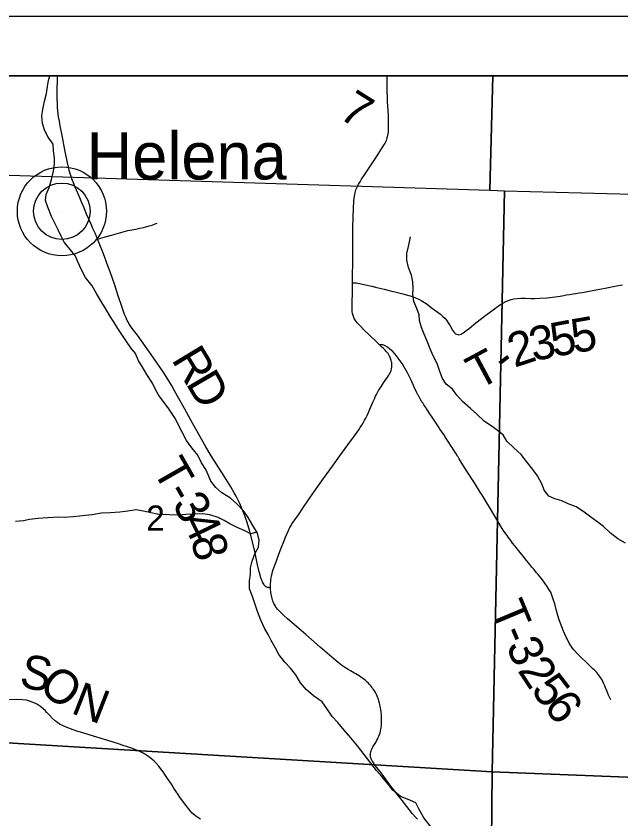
# Model space of a CAD drawing. Extents: x 0 to 34, y 0 to 22.
# Drawn here: x 25.305 to 26.316, y 19.658 to 21 of the extents above; entities that cross this region are included whole.
import ezdxf

# ---------------------------------------------------------------- set-up
doc = ezdxf.new("R2010")
doc.units = 0
for name, color, linetype in [('GM_X_Corporation', 7, 'Continuous'), ('GM_X_County_Road', 7, 'Continuous'), ('GM_X_County_Road_Text', 7, 'Continuous'), ('GM_X_Minor_River', 7, 'Continuous'), ('GM_X_Section_Text', 7, 'Continuous'), ('GM_X_Township_Road', 7, 'Continuous'), ('GM_X_Township_Road_Text', 7, 'Continuous'), ('GM_X_Unincorporated', 7, 'Continuous'), ('GM_X_Unincorporated_Location', 7, 'Continuous'), ('GM_X_Unincorporated_Text', 7, 'Continuous'), ('SH_Data', 7, 'Continuous')]:
    doc.layers.add(name, color=color, linetype=linetype)

msp = doc.modelspace()

# ---------------------------------------------------------------- linework, layer by layer
at = {"layer": 'GM_X_Corporation'}
for points in [[(30.3167, 20.9), (23.5167, 20.9), (23.5167, 14.7114), (24.6586, 14.6808), (24.6805, 14.6799), (26.0522, 14.6391), (26.4447, 14.6283), (26.4468, 14.6272), (26.4498, 14.6263), (26.4544, 14.6257), (26.5226, 14.6248), (26.5325, 14.6248), (26.5616, 14.6241), (26.5684, 14.624), (26.5727, 14.624), (26.5813, 14.6239), (26.5991, 14.6234), (26.6128, 14.6229), (26.6208, 14.6225), (26.6337, 14.622), (26.643, 14.6216), (26.6535, 14.621), (27.01, 14.6164)], [(30.3167, 20.9), (25.1014, 20.9), (25.0988, 20.7425), (25.0847, 19.8351), (25.0701, 18.7696), (25.0668, 18.5474), (25.0619, 17.7438), (25.4012, 17.7333), (26.0747, 17.7146), (26.0759, 17.6934), (26.0745, 17.4524), (26.0677, 16.948), (26.0646, 16.863), (26.0683, 16.6823), (26.3378, 16.673), (27.0694, 16.6556)]]:
    msp.add_lwpolyline(points, dxfattribs=at)
for points in [[(26.1019, 20.9), (25.0987, 20.9), (25.0966, 20.7402), (26.0969, 20.7089)], [(27.1148, 20.9), (26.1019, 20.9), (26.0969, 20.7089), (26.1216, 20.708), (27.1086, 20.6823)], [(26.0969, 20.7089), (26.1216, 20.708), (26.1009, 19.7362), (25.0844, 19.7972), (25.0966, 20.7402)], [(26.1216, 20.708), (27.1086, 20.6823), (27.14, 20.6818), (27.1321, 19.6957), (26.1009, 19.7362)], [(25.0844, 19.7972), (26.1009, 19.7362), (26.0916, 18.7368), (25.0685, 18.7697)], [(27.1321, 19.6957), (27.1305, 19.6616), (27.1072, 18.6988), (26.0916, 18.7368), (26.1009, 19.7362)]]:
    msp.add_lwpolyline(points, close=True, dxfattribs=at)
at = {"layer": 'GM_X_County_Road'}
msp.add_line((25.9256, 20.8989), (25.9257, 20.9), dxfattribs=at)
for points in [[(25.8675, 20.554), (25.8676, 20.5639), (25.8681, 20.5894), (25.8682, 20.6066), (25.8681, 20.6285), (25.8681, 20.6456), (25.8687, 20.6647), (25.8692, 20.6777), (25.8699, 20.6908), (25.8706, 20.6987), (25.8711, 20.7017), (25.8717, 20.7048), (25.8724, 20.7072), (25.8731, 20.7094), (25.874, 20.7117), (25.875, 20.7141), (25.8762, 20.7163), (25.8776, 20.7189), (25.88, 20.723), (25.8825, 20.727), (25.8874, 20.7346), (25.9029, 20.7578), (25.9088, 20.7665), (25.915, 20.7761), (25.9182, 20.7812), (25.92, 20.7842), (25.9219, 20.7874), (25.9231, 20.7897), (25.9241, 20.7919), (25.9249, 20.7942), (25.9256, 20.7962), (25.9262, 20.7983), (25.9267, 20.8006), (25.9271, 20.8031), (25.9274, 20.8057), (25.9276, 20.8086), (25.9277, 20.8144), (25.9277, 20.8223), (25.9275, 20.8322), (25.927, 20.8428), (25.9267, 20.849), (25.9262, 20.8576), (25.9258, 20.8667), (25.9255, 20.8717), (25.9254, 20.8754), (25.9253, 20.8791), (25.9256, 20.8989)], [(25.9128, 20.4502), (25.9088, 20.454), (25.8939, 20.468), (25.8873, 20.4745), (25.8797, 20.4824), (25.8767, 20.4855), (25.8753, 20.487), (25.874, 20.4888), (25.8725, 20.4908), (25.8712, 20.4928), (25.8703, 20.4944), (25.8696, 20.496), (25.8689, 20.4975), (25.8683, 20.4993), (25.8678, 20.501), (25.8674, 20.5028), (25.8671, 20.5058), (25.8669, 20.5082), (25.8669, 20.5107), (25.867, 20.5192), (25.8673, 20.539), (25.8675, 20.554)], [(25.7302, 20.0443), (25.7302, 20.046), (25.7303, 20.0483), (25.7304, 20.0513), (25.7306, 20.0545), (25.7309, 20.0573), (25.7314, 20.0605), (25.732, 20.064), (25.7328, 20.0678), (25.7337, 20.0713), (25.7348, 20.0749), (25.7384, 20.0848), (25.7437, 20.0987), (25.7478, 20.1091), (25.7528, 20.1217), (25.7556, 20.1286), (25.7604, 20.1397), (25.7617, 20.1427), (25.7627, 20.1447), (25.7637, 20.1466), (25.7646, 20.1482), (25.7662, 20.1508), (25.7682, 20.1539), (25.7718, 20.1591), (25.7757, 20.1645), (25.7854, 20.1787), (25.8013, 20.2016), (25.8191, 20.2266), (25.8338, 20.2474), (25.8463, 20.2645), (25.8597, 20.2831), (25.8708, 20.2981), (25.878, 20.3083), (25.8804, 20.312), (25.883, 20.3161), (25.8853, 20.3199), (25.8877, 20.3242), (25.8895, 20.3278), (25.8917, 20.3319), (25.8942, 20.3374), (25.8965, 20.3426), (25.9016, 20.3545), (25.9045, 20.3613), (25.906, 20.3646), (25.9075, 20.3675), (25.9085, 20.3697), (25.9097, 20.3719), (25.9109, 20.374), (25.9124, 20.3763), (25.9158, 20.3812), (25.9195, 20.3866), (25.9234, 20.3923), (25.9262, 20.3962), (25.9284, 20.3995), (25.9295, 20.4016), (25.9305, 20.4036), (25.9314, 20.4057), (25.932, 20.4076), (25.9324, 20.4094), (25.9327, 20.411), (25.9329, 20.4126), (25.9331, 20.4146), (25.9331, 20.4164), (25.9331, 20.4182), (25.9329, 20.4202), (25.9326, 20.422), (25.9322, 20.4239), (25.9317, 20.4258), (25.9311, 20.4276), (25.9305, 20.429), (25.9298, 20.4305), (25.9289, 20.4321), (25.928, 20.4338), (25.9268, 20.4356), (25.9255, 20.4374), (25.9239, 20.4392), (25.9222, 20.4411), (25.9194, 20.4439), (25.916, 20.4472), (25.9128, 20.4502)], [(25.9761, 19.6569), (25.9732, 19.6601), (25.968, 19.6662), (25.9487, 19.6904), (25.9316, 19.7123), (25.9154, 19.7346), (25.9082, 19.7435), (25.9053, 19.7471), (25.9024, 19.7512), (25.9007, 19.7539), (25.8997, 19.7555), (25.8989, 19.757), (25.8984, 19.7584), (25.8979, 19.7598), (25.8976, 19.7609), (25.8974, 19.762), (25.8973, 19.763), (25.8972, 19.7641), (25.8972, 19.7651), (25.8973, 19.7661), (25.8974, 19.7671), (25.8976, 19.7681), (25.8978, 19.7691), (25.8981, 19.7701), (25.8984, 19.7711), (25.8987, 19.772), (25.8991, 19.773), (25.8996, 19.7741), (25.9004, 19.7759), (25.9015, 19.7779), (25.9063, 19.7855), (25.9083, 19.7891), (25.9094, 19.7912), (25.9105, 19.7936), (25.9115, 19.7961), (25.9125, 19.7987), (25.9134, 19.8017), (25.914, 19.8043), (25.9147, 19.8075), (25.9152, 19.8105), (25.9157, 19.814), (25.916, 19.8171), (25.9161, 19.8205), (25.9161, 19.8243), (25.916, 19.8279), (25.9158, 19.8315), (25.9154, 19.836), (25.9149, 19.8399), (25.9143, 19.8434), (25.9139, 19.8459), (25.9133, 19.8483), (25.9125, 19.8515), (25.9117, 19.8544), (25.9106, 19.8576), (25.9096, 19.8603), (25.9085, 19.8629), (25.9073, 19.8655), (25.9056, 19.8687), (25.904, 19.8716), (25.9025, 19.8738), (25.9011, 19.8757), (25.8996, 19.8777), (25.8978, 19.88), (25.896, 19.8821), (25.8939, 19.8844), (25.8922, 19.886), (25.8903, 19.8878), (25.8884, 19.8895), (25.8864, 19.8911), (25.8839, 19.893), (25.8813, 19.8948), (25.8786, 19.8966), (25.8755, 19.8985), (25.8729, 19.9001), (25.8699, 19.9018), (25.8642, 19.905), (25.8599, 19.9076), (25.8558, 19.9103), (25.8525, 19.9125), (25.8492, 19.9149), (25.8463, 19.9171), (25.8433, 19.9194), (25.8329, 19.9281), (25.8135, 19.9446), (25.7991, 19.9575), (25.7894, 19.9661), (25.7661, 19.9858), (25.7587, 19.9921), (25.7526, 19.9977), (25.7493, 20.0008), (25.7464, 20.0037), (25.7441, 20.0061), (25.7422, 20.0082), (25.7404, 20.0105), (25.7389, 20.0126), (25.7378, 20.0143), (25.7368, 20.016), (25.7359, 20.0178), (25.7351, 20.0196), (25.7342, 20.0217), (25.7334, 20.0241), (25.7328, 20.0262), (25.7323, 20.0282), (25.7317, 20.0309), (25.7313, 20.0336), (25.7309, 20.036), (25.7306, 20.0384), (25.7304, 20.0408), (25.7303, 20.0425), (25.7302, 20.0443)], [(25.6131, 19.6574), (25.6088, 19.6597), (25.6052, 19.662), (25.6024, 19.6642), (25.5993, 19.6671), (25.5964, 19.6703), (25.5885, 19.6806), (25.5829, 19.688), (25.5786, 19.6941), (25.5746, 19.7003), (25.5732, 19.7024), (25.5688, 19.7091), (25.5657, 19.7138), (25.5623, 19.719), (25.5591, 19.7235), (25.557, 19.7266), (25.5537, 19.732), (25.5506, 19.7364), (25.5465, 19.7419), (25.5434, 19.7458), (25.5389, 19.751), (25.5357, 19.7541), (25.5315, 19.7578), (25.5245, 19.7631), (25.5176, 19.7674), (25.512, 19.7702), (25.5051, 19.7731), (25.4976, 19.7761), (25.4894, 19.7787), (25.4841, 19.7804), (25.4758, 19.7831), (25.4657, 19.7862), (25.4396, 19.7943), (25.4123, 19.8025), (25.408, 19.8038), (25.4001, 19.8064), (25.3886, 19.8109), (25.3824, 19.8136), (25.3775, 19.8162), (25.3739, 19.8186), (25.3706, 19.8212), (25.3656, 19.8257), (25.36, 19.8314), (25.3564, 19.8358), (25.3534, 19.8389), (25.3501, 19.8419), (25.3457, 19.8454), (25.3421, 19.8479), (25.3393, 19.8495), (25.336, 19.8512), (25.3319, 19.8529), (25.3271, 19.8546), (25.3223, 19.8559), (25.3158, 19.8568), (25.3077, 19.8572), (25.2872, 19.8567)]]:
    msp.add_lwpolyline(points, dxfattribs=at)
at = {"layer": 'GM_X_Minor_River'}
for points in [[(25.3528, 20.8082), (25.3489, 20.8203), (25.348, 20.8339), (25.3494, 20.8438), (25.3523, 20.8575), (25.3556, 20.8704), (25.3574, 20.8822), (25.3592, 20.8921), (25.3611, 20.9)], [(26.0065, 19.6339), (25.9867, 19.6594), (25.9786, 19.6745), (25.9732, 19.6843), (25.9592, 19.6906), (25.9474, 19.695), (25.9348, 19.7055), (25.9276, 19.7153), (25.9157, 19.7288), (25.9073, 19.7386), (25.8978, 19.751), (25.8871, 19.7652), (25.8756, 19.7799), (25.8645, 19.7934), (25.8534, 19.8058), (25.8427, 19.819), (25.8332, 19.8291), (25.8255, 19.8408), (25.8167, 19.8532), (25.8019, 19.8636), (25.7901, 19.8741), (25.7806, 19.885), (25.7725, 19.8986), (25.7637, 19.9095), (25.7542, 19.9196), (25.7442, 19.9324), (25.7381, 19.9444), (25.7315, 19.9561), (25.7265, 19.9659), (25.72, 19.9768), (25.7139, 19.99), (25.7084, 20.0044), (25.7038, 20.0176), (25.6999, 20.0293), (25.6952, 20.0425), (25.6951, 20.0557), (25.6969, 20.0671), (25.6968, 20.0774), (25.6994, 20.0884), (25.7042, 20.1006), (25.7101, 20.112), (25.7115, 20.1237), (25.7084, 20.1355), (25.7007, 20.1483), (25.6931, 20.1618), (25.6858, 20.1724), (25.674, 20.1844), (25.6633, 20.1937), (25.6489, 20.203), (25.6389, 20.212), (25.6305, 20.2222), (25.6267, 20.232), (25.6221, 20.2418), (25.6148, 20.2531), (25.609, 20.2659), (25.5987, 20.2783), (25.5899, 20.2903), (25.5818, 20.3054), (25.5703, 20.328), (25.5603, 20.3431), (25.5526, 20.354), (25.5438, 20.3653), (25.5381, 20.3758), (25.5331, 20.3864), (25.5235, 20.4007), (25.5154, 20.4139), (25.5093, 20.4236), (25.5043, 20.4357), (25.4966, 20.4455), (25.4894, 20.456), (25.4748, 20.4775), (25.469, 20.4877), (25.4614, 20.4986), (25.4556, 20.5095), (25.4483, 20.5208), (25.4395, 20.5362), (25.4318, 20.5487), (25.4211, 20.5626), (25.4138, 20.5769), (25.408, 20.589), (25.4042, 20.5988), (25.3958, 20.6089), (25.3851, 20.6217), (25.3804, 20.6319), (25.3754, 20.6424), (25.3639, 20.6651), (25.3577, 20.6802), (25.3542, 20.6915), (25.3549, 20.7014), (25.3601, 20.7132), (25.3641, 20.7265), (25.3674, 20.7405), (25.3688, 20.753), (25.3691, 20.7625), (25.3671, 20.7746), (25.367, 20.786), (25.3582, 20.7977), (25.3528, 20.8082)], [(26.324, 20.1188), (26.3111, 20.1259), (26.2985, 20.136), (26.2871, 20.1465), (26.276, 20.1551), (26.2638, 20.1637), (26.2524, 20.1723), (26.2414, 20.1794), (26.2278, 20.1845), (26.2175, 20.1893), (26.2058, 20.1926), (26.1959, 20.1971), (26.1879, 20.2072), (26.1847, 20.217), (26.1767, 20.231), (26.169, 20.2419), (26.1583, 20.2554), (26.1492, 20.2671), (26.1373, 20.2783), (26.1255, 20.2892), (26.1194, 20.2997), (26.1034, 20.312), (26.0874, 20.3225), (26.0752, 20.3345), (26.0649, 20.3439), (26.0516, 20.3558), (26.0417, 20.3663), (26.0348, 20.3761), (26.0241, 20.3844), (26.018, 20.3941), (26.0137, 20.4058), (26.0091, 20.4191), (26.0025, 20.4319), (25.9971, 20.4436), (25.9925, 20.4564), (25.9871, 20.4681), (25.9828, 20.4794), (25.9797, 20.4908), (25.9789, 20.5006), (25.975, 20.5108), (25.97, 20.5225), (25.9684, 20.5342), (25.969, 20.5441), (25.9682, 20.5554), (25.9658, 20.5668), (25.9612, 20.5796), (25.958, 20.5917), (25.9583, 20.6031), (25.9608, 20.6149), (25.963, 20.6251), (25.9645, 20.6308)], [(25.7075, 20.137), (25.6971, 20.1342), (25.6861, 20.1398), (25.6743, 20.1446), (25.6625, 20.1509), (25.653, 20.1565), (25.6428, 20.1613), (25.6288, 20.1661), (25.617, 20.1675), (25.6008, 20.1669), (25.5887, 20.1668), (25.5774, 20.1652), (25.5607, 20.1661), (25.5433, 20.1667), (25.5301, 20.1692), (25.5206, 20.1718), (25.5058, 20.1743), (25.4915, 20.1722), (25.4783, 20.1706), (25.4624, 20.1696), (25.4477, 20.1687), (25.4318, 20.1659), (25.4209, 20.1647), (25.4111, 20.1638), (25.4005, 20.1629), (25.385, 20.1616), (25.3752, 20.1619), (25.3578, 20.161), (25.3415, 20.16), (25.3272, 20.158), (25.3174, 20.156), (25.3038, 20.1547)]]:
    msp.add_lwpolyline(points, dxfattribs=at)
at = {"layer": 'GM_X_Township_Road'}
for points in [[(25.4411, 20.6272), (25.4374, 20.636), (25.4334, 20.6449), (25.4297, 20.6533), (25.4266, 20.6603), (25.4227, 20.669), (25.4185, 20.6792), (25.416, 20.6855), (25.4138, 20.6906), (25.4113, 20.6962), (25.4078, 20.7041), (25.4035, 20.7141), (25.4019, 20.7181), (25.398, 20.7279), (25.3957, 20.735), (25.3942, 20.7403), (25.393, 20.7451), (25.3908, 20.7548), (25.3864, 20.7761), (25.3823, 20.7975), (25.3786, 20.8164), (25.3773, 20.824), (25.376, 20.8317), (25.3748, 20.8415), (25.3743, 20.8479), (25.3738, 20.8539), (25.3735, 20.8613), (25.3736, 20.8756), (25.3741, 20.8948), (25.3741, 20.9)], [(25.9256, 20.8989), (25.9228, 20.8994), (25.9195, 20.9)], [(25.4411, 20.6272), (25.4466, 20.6289), (25.4536, 20.6309), (25.4643, 20.6337), (25.4839, 20.6393), (25.4916, 20.6412), (25.4983, 20.6426), (25.505, 20.6439), (25.5117, 20.6451), (25.5177, 20.6464), (25.5218, 20.6475), (25.5271, 20.649), (25.5323, 20.6506), (25.5375, 20.6524), (25.541, 20.6536)], [(25.7302, 20.0443), (25.7283, 20.0442), (25.7272, 20.0443), (25.7261, 20.0444), (25.725, 20.0446), (25.7241, 20.0449), (25.7232, 20.0454), (25.7223, 20.0459), (25.7215, 20.0467), (25.7207, 20.0475), (25.7198, 20.0487), (25.7189, 20.05), (25.7181, 20.0515), (25.7171, 20.0533), (25.7162, 20.0555), (25.7152, 20.058), (25.7143, 20.0606), (25.7135, 20.0632), (25.7115, 20.071), (25.7088, 20.0826), (25.7039, 20.105), (25.7001, 20.1207), (25.6955, 20.1381), (25.6911, 20.153), (25.6874, 20.1642), (25.6858, 20.1687), (25.6842, 20.1729), (25.6825, 20.1768), (25.6807, 20.1809), (25.6782, 20.1862), (25.6755, 20.1915), (25.6726, 20.1971), (25.6694, 20.203), (25.6637, 20.2127), (25.6526, 20.2306), (25.6312, 20.2649), (25.6224, 20.2799), (25.6001, 20.3194), (25.5865, 20.3437), (25.5699, 20.3736), (25.5647, 20.3828), (25.5586, 20.3929), (25.5505, 20.4054), (25.5348, 20.4285), (25.5076, 20.4663), (25.4992, 20.4778), (25.4936, 20.4861), (25.4922, 20.4885), (25.4908, 20.4909), (25.4893, 20.4938), (25.4881, 20.4965), (25.4867, 20.4997), (25.4855, 20.5028), (25.4821, 20.5128), (25.4751, 20.5341), (25.4699, 20.55), (25.4619, 20.5722), (25.4583, 20.5821), (25.4509, 20.6025), (25.4439, 20.6205), (25.4411, 20.6272)], [(25.8675, 20.554), (25.8683, 20.554), (25.8707, 20.5539), (25.8722, 20.5539), (25.8737, 20.5537), (25.8762, 20.5535), (25.8892, 20.5507), (25.9, 20.5481), (25.906, 20.5466), (25.9156, 20.5443), (25.9204, 20.5431), (25.9264, 20.5417), (25.9425, 20.5379), (25.9449, 20.5373), (25.9515, 20.5355), (25.9616, 20.5327), (25.9675, 20.5309), (25.9728, 20.529), (25.9784, 20.5265), (25.9823, 20.5244), (25.9876, 20.5212), (25.9922, 20.5181), (25.9957, 20.5155), (25.9991, 20.5129), (26.0066, 20.5073), (26.0145, 20.5013), (26.0187, 20.4976), (26.0218, 20.4946), (26.0246, 20.4913), (26.0275, 20.4872), (26.0307, 20.4819), (26.0347, 20.4749), (26.0364, 20.4723), (26.038, 20.4704), (26.0399, 20.4689), (26.0415, 20.468), (26.0433, 20.4674), (26.0445, 20.4672), (26.0469, 20.4674), (26.0492, 20.4683), (26.0523, 20.4702), (26.0593, 20.4752), (26.0631, 20.4783), (26.0735, 20.4869), (26.0831, 20.4945), (26.0925, 20.5016), (26.1025, 20.5089), (26.1131, 20.5164), (26.1189, 20.52), (26.1238, 20.5227), (26.1284, 20.5246), (26.1325, 20.5259), (26.1374, 20.527), (26.1429, 20.5278), (26.1491, 20.5283), (26.1559, 20.5284), (26.1659, 20.5279), (26.1721, 20.5278), (26.1807, 20.5281), (26.193, 20.5291), (26.1972, 20.5295), (26.2063, 20.5306), (26.2149, 20.5319), (26.2173, 20.5323), (26.221, 20.5329), (26.2253, 20.5336), (26.2302, 20.5344), (26.2363, 20.5355), (26.2406, 20.5362), (26.2467, 20.5372), (26.2516, 20.538), (26.2546, 20.5386), (26.2717, 20.5416), (26.2809, 20.5433), (26.2925, 20.5455), (26.3089, 20.5488), (26.3187, 20.5505)], [(26.2994, 19.8568), (26.2957, 19.8647), (26.293, 19.8709), (26.2916, 19.8743), (26.2907, 19.8766), (26.2898, 19.8787), (26.2893, 19.8799), (26.2886, 19.8815), (26.2881, 19.8826), (26.2877, 19.8837), (26.2862, 19.8871), (26.2847, 19.89), (26.2828, 19.893), (26.2812, 19.8956), (26.279, 19.8986), (26.277, 19.9009), (26.2758, 19.9023), (26.2742, 19.9041), (26.2716, 19.9068), (26.2693, 19.9088), (26.2671, 19.911), (26.2644, 19.9135), (26.2622, 19.9157), (26.2604, 19.9173), (26.2568, 19.9207), (26.2523, 19.925), (26.2435, 19.9338), (26.2381, 19.9397), (26.2354, 19.9431), (26.2329, 19.9467), (26.23, 19.9515), (26.2262, 19.9586), (26.2248, 19.9613), (26.2226, 19.9665), (26.2204, 19.9716), (26.2173, 19.979), (26.2132, 19.9907), (26.211, 19.9978), (26.2082, 20.008), (26.2057, 20.017), (26.2032, 20.0253), (26.201, 20.0317), (26.1995, 20.0351), (26.1988, 20.0366), (26.1964, 20.0409), (26.1931, 20.0461), (26.1849, 20.0571), (26.1777, 20.0665), (26.1753, 20.0693), (26.1706, 20.075), (26.1674, 20.0788), (26.1638, 20.0831), (26.1619, 20.0855), (26.1564, 20.0923), (26.1532, 20.0961), (26.1478, 20.1029), (26.1455, 20.1058), (26.1444, 20.1072), (26.1417, 20.1107), (26.1391, 20.1141), (26.1352, 20.1189), (26.1334, 20.1214), (26.1323, 20.1229), (26.13, 20.1258), (26.1278, 20.1288), (26.126, 20.1313), (26.1242, 20.1338), (26.1206, 20.1388), (26.115, 20.1477), (26.1087, 20.1584), (26.1055, 20.1638), (26.104, 20.1665), (26.0982, 20.176), (26.0921, 20.1861), (26.0836, 20.1998), (26.081, 20.2041), (26.0715, 20.2194), (26.0672, 20.2262), (26.0632, 20.2325), (26.0588, 20.2392), (26.049, 20.2543), (26.0458, 20.2596), (26.0439, 20.2628), (26.0429, 20.2644), (26.0405, 20.2679), (26.0356, 20.2758), (26.0339, 20.2784), (26.0323, 20.281), (26.0273, 20.2889), (26.0252, 20.292), (26.0222, 20.2966), (26.0199, 20.3002), (26.0178, 20.3033), (26.0158, 20.3064), (26.0137, 20.3093), (26.0125, 20.3113), (26.0105, 20.3141), (26.0089, 20.3166), (26.0072, 20.3192), (26.0015, 20.3279), (25.9995, 20.331), (25.9981, 20.333), (25.9926, 20.3412), (25.9905, 20.3442), (25.9899, 20.3453), (25.9869, 20.35), (25.9849, 20.3531), (25.9835, 20.3552), (25.9807, 20.3599), (25.9776, 20.3653), (25.9767, 20.3669), (25.9755, 20.369), (25.9744, 20.3711), (25.9711, 20.3782), (25.9653, 20.3913), (25.9595, 20.4032), (25.9551, 20.4114), (25.9505, 20.4188), (25.944, 20.4281), (25.9386, 20.4345), (25.9346, 20.4389), (25.9301, 20.4433), (25.9262, 20.4463), (25.9223, 20.4486), (25.92, 20.4496), (25.9182, 20.4502), (25.9166, 20.4505), (25.9149, 20.4505), (25.9128, 20.4502)]]:
    msp.add_lwpolyline(points, dxfattribs=at)
at = {"layer": 'GM_X_Unincorporated'}
for radius in [0.0744, 0.0472]:
    msp.add_circle((25.3814, 20.6736), radius, dxfattribs=at)
at = {"layer": 'GM_X_Unincorporated_Location'}
msp.add_line((25.3814, 20.6736), (25.3814, 20.6736), dxfattribs=at)
at = {"layer": 'SH_Data'}
for points in [[(23.4167, 21), (30.4167, 21), (30.4167, 14), (23.4167, 14)], [(23.5167, 20.9), (30.3167, 20.9), (30.3167, 14.1), (23.5167, 14.1)]]:
    msp.add_lwpolyline(points, close=True, dxfattribs=at)

# ---------------------------------------------------------------- texts
at = {"layer": 'GM_X_County_Road_Text'}
for s, rotation, p in [('S', 348.1389, (25.3084, 19.8792)), ('O', 322.6303, (25.3399, 19.8741)), ('N', 338.6114, (25.3947, 19.8353))]:
    msp.add_text(s, height=0.0568, rotation=rotation, dxfattribs=at).set_placement(p)
at = {"layer": 'GM_X_Section_Text'}
msp.add_text('2', height=0.0419, rotation=0, dxfattribs=at).set_placement((25.5224, 20.1397))
at = {"layer": 'GM_X_Township_Road_Text'}
for s, rotation, p in [('7', 327.7564, (25.8422, 20.8312)), ('5', 10.5087, (26.2036, 20.4296)), ('5', 9.7207, (26.2378, 20.436)), ('2', 18.2251, (26.1381, 20.4118)), ('3', 12.2122, (26.1698, 20.4223)), ('R', 301.1063, (25.5637, 20.4258)), ('T', 28.0985, (26.0779, 20.3743)), ('-', 37.6836, (26.1241, 20.3999)), ('D', 300.3359, (25.5877, 20.386)), ('T', 299.7885, (25.5322, 20.2412)), ('3', 299.7423, (25.5649, 20.184)), ('-', 299.7903, (25.5533, 20.2043)), ('4', 295.8354, (25.5818, 20.1546)), ('8', 285.9097, (25.5961, 20.1255)), ('T', 292.6753, (26.0976, 20.0088)), ('-', 292.8123, (26.1141, 19.9695)), ('3', 293.7361, (26.1235, 19.9471)), ('2', 303.3064, (26.1425, 19.9059)), ('5', 307.4465, (26.1643, 19.873)), ('6', 307.4179, (26.1856, 19.8453))]:
    msp.add_text(s, height=0.0568, rotation=rotation, dxfattribs=at).set_placement(p)
at = {"layer": 'GM_X_Unincorporated_Text'}
msp.add_text('Helena', height=0.07898, rotation=0, dxfattribs=at).set_placement((25.4228, 20.7268))

doc.saveas('drawing.dxf')
